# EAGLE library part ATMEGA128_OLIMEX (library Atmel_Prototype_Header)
MICROCONTROLLER 128 Kbytes FLASH 4 Kbytes SRAM 4 Kbytes EEPROM DUAL USART 8-channel 10 bit ADC
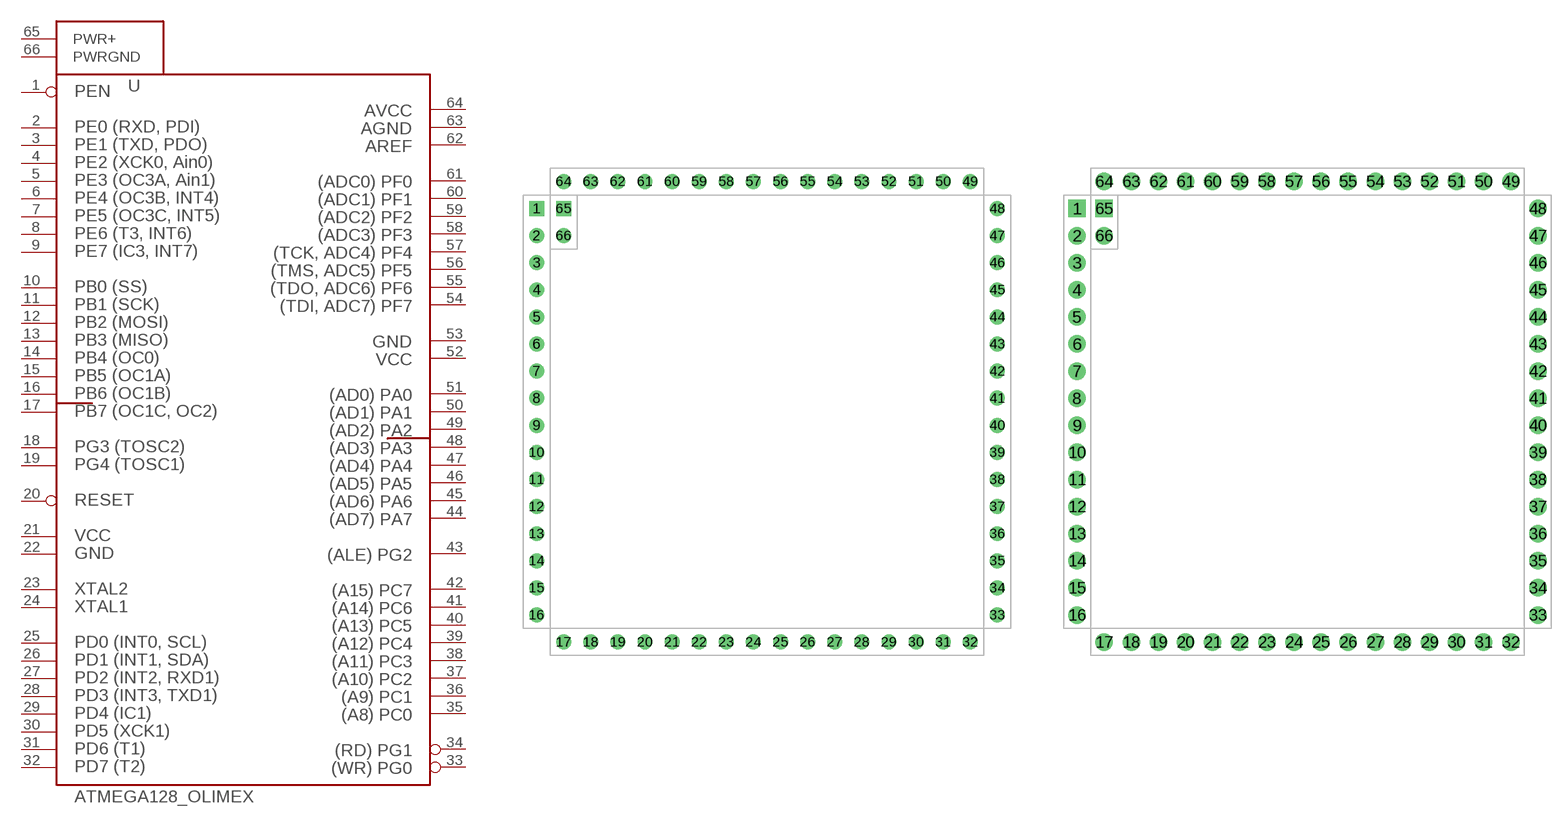
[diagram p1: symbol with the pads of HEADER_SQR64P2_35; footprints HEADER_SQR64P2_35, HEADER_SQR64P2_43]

Designator prefix U

## ATMEGA128_OLIMEX_SINGLE66_35  [HEADER_SQR64P2_35]
1  1  in
2  2
3  3
4  4
5  5
6  6
7  7
8  8
9  9
10  10
11  11
12  12
13  13
14  14
15  15
16  16
17  17
18  18
19  19
20  20  in
21  21  pwr
22  22  pwr
23  23
24  24
25  25
26  26
27  27
28  28
29  29
30  30
31  31
32  32
33  33
34  34
35  35  out
36  36  out
37  37  out
38  38  out
39  39  out
40  40  out
41  41  out
42  42  out
43  43
44  44
45  45
46  46
47  47
48  48
49  49
50  50
51  51
52  52  pwr
53  53  pwr
54  54  in
55  55  in
56  56  in
57  57  in
58  58  in
59  59  in
60  60  in
61  61  in
62  62
63  63
64  64
65  PWR+
66  PWRGND

## ATMEGA128_OLIMEX_SINGLE66_43  [HEADER_SQR64P2_43]
Pads as for HEADER_SQR64P2_35

## Footprint HEADER_SQR64P2_35 (pad centres in mm)
drill 0.889 square: 1 -21.59,19.05; 65 -19.05,19.05
drill 0.889 round: 2 -21.59,16.51; 3 -21.59,13.97; 4 -21.59,11.43; 5 -21.59,8.89; 6 -21.59,6.35; 7 -21.59,3.81; 8 -21.59,1.27; 9 -21.59,-1.27; 10 -21.59,-3.81; 11 -21.59,-6.35; 12 -21.59,-8.89; 13 -21.59,-11.43; 14 -21.59,-13.97; 15 -21.59,-16.51; 16 -21.59,-19.05; 17 -19.05,-21.59; 18 -16.51,-21.59; 19 -13.97,-21.59; 20 -11.43,-21.59; 21 -8.89,-21.59; 22 -6.35,-21.59; 23 -3.81,-21.59; 24 -1.27,-21.59; 25 1.27,-21.59; 26 3.81,-21.59; 27 6.35,-21.59; 28 8.89,-21.59; 29 11.43,-21.59; 30 13.97,-21.59; 31 16.51,-21.59; 32 19.05,-21.59; 33 21.59,-19.05; 34 21.59,-16.51; 35 21.59,-13.97; 36 21.59,-11.43; 37 21.59,-8.89; 38 21.59,-6.35; 39 21.59,-3.81; 40 21.59,-1.27; 41 21.59,1.27; 42 21.59,3.81; 43 21.59,6.35; 44 21.59,8.89; 45 21.59,11.43; 46 21.59,13.97; 47 21.59,16.51; 48 21.59,19.05; 49 19.05,21.59; 50 16.51,21.59; 51 13.97,21.59; 52 11.43,21.59; 53 8.89,21.59; 54 6.35,21.59; 55 3.81,21.59; 56 1.27,21.59; 57 -1.27,21.59; 58 -3.81,21.59; 59 -6.35,21.59; 60 -8.89,21.59; 61 -11.43,21.59; 62 -13.97,21.59; 63 -16.51,21.59; 64 -19.05,21.59; 66 -19.05,16.51

## Footprint HEADER_SQR64P2_43 (pad centres in mm)
drill 1.092 square: 1 -21.59,19.05; 65 -19.05,19.05
drill 1.092 round: 2 -21.59,16.51; 3 -21.59,13.97; 4 -21.59,11.43; 5 -21.59,8.89; 6 -21.59,6.35; 7 -21.59,3.81; 8 -21.59,1.27; 9 -21.59,-1.27; 10 -21.59,-3.81; 11 -21.59,-6.35; 12 -21.59,-8.89; 13 -21.59,-11.43; 14 -21.59,-13.97; 15 -21.59,-16.51; 16 -21.59,-19.05; 17 -19.05,-21.59; 18 -16.51,-21.59; 19 -13.97,-21.59; 20 -11.43,-21.59; 21 -8.89,-21.59; 22 -6.35,-21.59; 23 -3.81,-21.59; 24 -1.27,-21.59; 25 1.27,-21.59; 26 3.81,-21.59; 27 6.35,-21.59; 28 8.89,-21.59; 29 11.43,-21.59; 30 13.97,-21.59; 31 16.51,-21.59; 32 19.05,-21.59; 33 21.59,-19.05; 34 21.59,-16.51; 35 21.59,-13.97; 36 21.59,-11.43; 37 21.59,-8.89; 38 21.59,-6.35; 39 21.59,-3.81; 40 21.59,-1.27; 41 21.59,1.27; 42 21.59,3.81; 43 21.59,6.35; 44 21.59,8.89; 45 21.59,11.43; 46 21.59,13.97; 47 21.59,16.51; 48 21.59,19.05; 49 19.05,21.59; 50 16.51,21.59; 51 13.97,21.59; 52 11.43,21.59; 53 8.89,21.59; 54 6.35,21.59; 55 3.81,21.59; 56 1.27,21.59; 57 -1.27,21.59; 58 -3.81,21.59; 59 -6.35,21.59; 60 -8.89,21.59; 61 -11.43,21.59; 62 -13.97,21.59; 63 -16.51,21.59; 64 -19.05,21.59; 66 -19.05,16.51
